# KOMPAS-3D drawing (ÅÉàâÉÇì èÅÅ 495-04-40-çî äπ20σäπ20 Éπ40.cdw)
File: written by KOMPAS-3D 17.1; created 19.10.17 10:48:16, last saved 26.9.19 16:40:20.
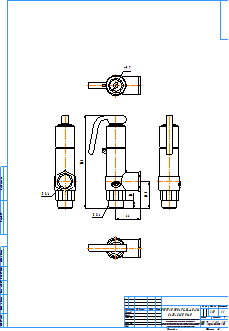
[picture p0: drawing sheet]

Sheet 1: A2, portrait

Title block, sheet 1: name: ПРЕГРАН КПП 495-04-40-ЗМ / Ду20хДу20 Ру40; material: Сталь 20  ГОСТ 1050-2013; mass: 1,10; sheets: 1; sheet format: A2; stored path: C:\Users\kka\KOMPAS_Work\!Trash\Прегран КПП 495\ПРЕГРАН КПП 495-04-40-ЗМ\KOMPAS 2D\Прегран КПП 495 Ду20хДу20 Ру40.cdw

Views: Спереди 6, Проекционный вид 7, Проекционный вид 8, Проекционный вид 9, Проекционный вид 10
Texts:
  kka
  adl
  Рама для чертежей
  Лит-Масса-Масштаб
  Материал-Предприятие
  Масштаб
  Изм.
  Лист
  № докум.
  Подп.
  Дата
  Лит.
  Разраб.
  Пров.
  Т.контр.
  Листов
  Внимание! Данный продукт является объектом авторского права ООО «Торговый Дом АДЛ».
  Запрещается изменение, копирование, распространение
  (в том числе путем копирования на другие сайты и ресурсы в Интернете)
  или любое иное использование информации и объектов без предварительного
  согласия правообладателя (ООО «Торговый Дом АДЛ»).
  Н.контр.
  Утв.
  ООО "Торговый дом АДЛ"
  Изменение
  Номер документа
  Подпись
  Обозначение документа
  Наименование изделия
  Масса изделия по ГОСТ 2.109-73
  Порядковый номер листа
  Общее количество листов в документе
  Характер работы, выполненной лицом, подписавшим документ
  Наименование или индекс предприятия, выпускающего документ
  Инв. № подл.
  Подп. и дата
  Взам. инв. №
  Инв. № дубл.
  Инвентарный номер подлинника по ГОСТ 2.501-68
  Подпись принявшего подлинник в отдел технической документации
  Инвентарный номер подлинника, взамен которого выпущен данный подлинник
  Инвентарный номер дубликата по ГОСТ 2.502-68
  Подпись принявшего дубликат в отдел технической документации
  Справ. №
  Перв. примен.
  Обозначение документа, взамен или на основании которого выпущен данный документ
  Обозначение документа, в котором впервые записан данный документ
  Подпись лица, копировавшего чертеж
  Обозначение формата листа
  !Рама для чертежа
Dimensions and other numbers on the sheet: 48,5; 15; 44; 167; 9,7; 1,10; 1:1; 1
